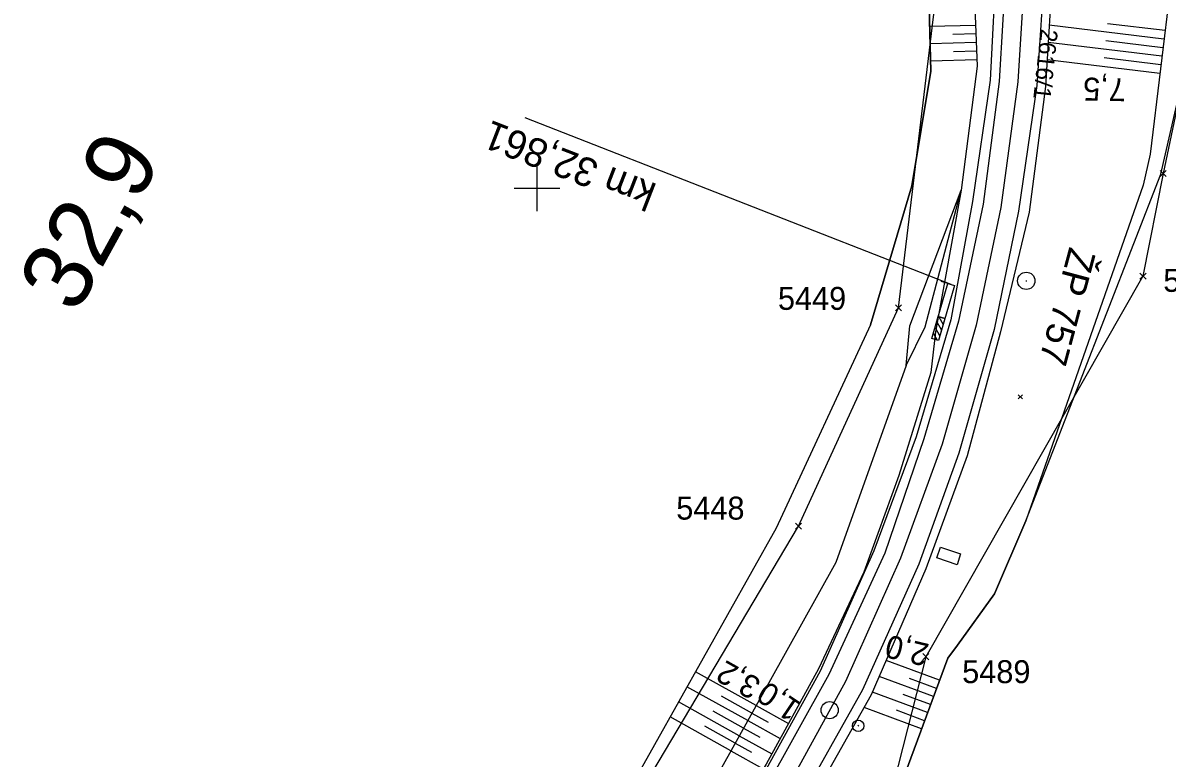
# Model space of a CAD drawing. Extents: x -804166 to -803706, y -1151030 to -1150147.
# Drawn here: x -803944.8 to -803845.1, y -1150649.7 to -1150585.6 of the extents above; entities that cross this region are included whole.
import ezdxf

# ---------------------------------------------------------------- set-up
doc = ezdxf.new("R2010")
doc.units = 0
for name, color, linetype in [('0381KM032-037P - Vrstva 1', 7, 'Continuous'), ('0381KM032-037P - Vrstva 17', 7, 'Continuous'), ('0381KM032-037P - Vrstva 4', 7, 'Continuous'), ('0381KM032-037P - Vrstva 48', 7, 'Continuous'), ('0381KM032-037P - Vrstva 49', 7, 'Continuous'), ('0381KM032-037P - Vrstva 50', 7, 'Continuous'), ('0381KM032-037P - Vrstva 51', 7, 'Continuous'), ('0381KM032-037P - Vrstva 57', 7, 'Continuous'), ('0381KM032-037P - Vrstva 6', 7, 'Continuous'), ('0381KM032-037P - Vrstva 7', 7, 'Continuous'), ('krizky_1000 - Vrstva 1', 7, 'Continuous'), ('szdc - hran DP', 7, 'Continuous'), ('szdc - szdc_cislo', 7, 'Continuous'), ('szdc - szdc_krizek', 7, 'Continuous'), ('vyt_sit - stávající', 7, 'Continuous')]:
    doc.layers.add(name, color=color, linetype=linetype)

msp = doc.modelspace()

# ---------------------------------------------------------------- linework, layer by layer
at = {"layer": '0381KM032-037P - Vrstva 1'}
msp.add_lwpolyline([(-803862.645, -1150536.71), (-803860.057, -1150547.81), (-803858.364, -1150558.718), (-803857.51, -1150569.546), (-803857.425, -1150579.975), (-803858.096, -1150590.725), (-803859.58, -1150601.687), (-803861.73, -1150611.946), (-803864.691, -1150622.329), (-803868.306, -1150632.261), (-803873.118, -1150643.006), (-803878.784, -1150653.323), (-803884.455, -1150662.043), (-803890.68, -1150670.289), (-803894.474, -1150674.768)], dxfattribs=at)
at = {"layer": '0381KM032-037P - Vrstva 17'}
msp.add_lwpolyline([(-803867.911, -1150651.01), (-803864.194, -1150640.965), (-803863.34, -1150639.848), (-803860.107, -1150635.351), (-803857.384, -1150629.008), (-803845.634, -1150598.77), (-803839.769, -1150573.178), (-803837.289, -1150572.72)], dxfattribs=at)
at = {"layer": '0381KM032-037P - Vrstva 4'}
for points in [[(-803872.779, -1150506.875), (-803867.872, -1150516.171), (-803864.004, -1150525.679), (-803860.599, -1150536.286), (-803857.956, -1150547.888), (-803856.113, -1150558.65), (-803855.009, -1150569.422), (-803855.013, -1150580.14), (-803855.681, -1150591.137), (-803857.109, -1150602.102)], [(-803872.779, -1150506.875), (-803868.424, -1150516.34), (-803864.491, -1150525.922), (-803861.191, -1150536.397), (-803858.415, -1150547.949), (-803856.721, -1150558.765), (-803855.706, -1150569.464), (-803855.706, -1150580.041), (-803856.439, -1150591.045), (-803858.016, -1150602.009)], [(-803875.392, -1150508.511), (-803871.454, -1150517.68), (-803867.834, -1150527.236), (-803864.663, -1150537.291), (-803862.152, -1150548.382), (-803860.595, -1150558.999), (-803859.922, -1150569.628), (-803859.947, -1150579.801), (-803860.5, -1150590.58), (-803862.041, -1150601.171)], [(-803859.085, -1150579.867), (-803859.701, -1150590.693), (-803861.107, -1150601.386)], [(-803862.041, -1150601.171), (-803863.934, -1150611.478), (-803866.955, -1150621.666), (-803870.636, -1150631.623), (-803875.322, -1150642.112), (-803880.813, -1150652.073), (-803886.36, -1150660.761), (-803891.5, -1150667.581), (-803892.695, -1150669.921)], [(-803861.107, -1150601.386), (-803863.249, -1150611.592), (-803866.278, -1150621.841), (-803869.683, -1150631.826), (-803874.548, -1150642.393), (-803880.159, -1150652.477), (-803885.847, -1150661.208), (-803892.695, -1150669.921)], [(-803858.016, -1150602.009), (-803860.157, -1150612.315), (-803863.229, -1150623.106), (-803866.722, -1150632.775), (-803871.621, -1150643.742), (-803877.472, -1150654.13), (-803883.137, -1150662.978), (-803889.477, -1150671.458), (-803892.178, -1150675.246)], [(-803857.109, -1150602.102), (-803859.611, -1150612.518), (-803862.49, -1150623.34), (-803866.1, -1150633.182), (-803870.873, -1150644.181), (-803876.806, -1150654.687), (-803882.51, -1150663.405), (-803892.178, -1150675.246)]]:
    msp.add_lwpolyline(points, dxfattribs=at)
at = {"layer": '0381KM032-037P - Vrstva 48'}
for p, q in [((-803861.779, -1150585.81), (-803865.774, -1150585.917)), ((-803845.348, -1150587.012), (-803855.357, -1150585.806)), ((-803845.259, -1150586.267), (-803850.285, -1150585.662)), ((-803861.749, -1150586.559), (-803863.751, -1150586.613)), ((-803861.719, -1150587.309), (-803865.734, -1150587.416)), ((-803845.528, -1150588.501), (-803855.448, -1150587.306)), ((-803845.438, -1150587.757), (-803850.42, -1150587.157)), ((-803861.658, -1150588.808), (-803865.694, -1150588.916)), ((-803861.688, -1150588.058), (-803863.701, -1150588.112)), ((-803845.707, -1150589.991), (-803855.539, -1150588.806)), ((-803845.617, -1150589.246), (-803850.556, -1150588.651)), ((-803864.911, -1150642.902), (-803869.57, -1150641.178)), ((-803880.906, -1150645.106), (-803886.195, -1150642.162)), ((-803865.431, -1150644.309), (-803870.168, -1150642.556)), ((-803865.171, -1150643.606), (-803867.52, -1150642.736)), ((-803881.635, -1150646.417), (-803886.93, -1150643.47)), ((-803882.365, -1150647.727), (-803887.665, -1150644.777)), ((-803881.27, -1150645.761), (-803883.916, -1150644.289)), ((-803865.952, -1150645.716), (-803870.766, -1150643.934)), ((-803865.692, -1150645.012), (-803868.079, -1150644.129)), ((-803882, -1150647.072), (-803884.649, -1150645.598)), ((-803881.27, -1150645.76), (-803879.86, -1150646.545)), ((-803880.905, -1150645.105), (-803878.088, -1150646.673)), ((-803866.473, -1150647.123), (-803871.486, -1150645.267)), ((-803866.212, -1150646.419), (-803868.663, -1150645.512)), ((-803883.094, -1150649.038), (-803888.401, -1150646.085)), ((-803881.635, -1150646.416), (-803878.814, -1150647.986)), ((-803882.729, -1150648.383), (-803885.381, -1150646.907)), ((-803882.364, -1150647.726), (-803879.539, -1150649.299)), ((-803881.999, -1150647.071), (-803880.588, -1150647.857)), ((-803882.729, -1150648.382), (-803881.315, -1150649.168)), ((-803883.093, -1150649.037), (-803880.278, -1150650.604))]:
    msp.add_line(p, q, dxfattribs=at)
at = {"layer": '0381KM032-037P - Vrstva 49'}
for p, q in [((-803870.937, -1150611.902), (-803879.144, -1150629.624)), ((-803858.047, -1150618.024), (-803857.693, -1150618.376)), ((-803857.694, -1150618.023), (-803858.046, -1150618.377))]:
    msp.add_line(p, q, dxfattribs=at)
for points in [[(-803888.13, -1150522.065), (-803877.502, -1150535.708), (-803870.854, -1150543.675), (-803863.849, -1150556.524), (-803862.399, -1150570.315), (-803861.636, -1150589.369), (-803863.02, -1150600.178)], [(-803888.331, -1150532.703), (-803880.592, -1150540.151), (-803872.905, -1150546.743), (-803867.412, -1150556.856), (-803866.176, -1150570.896), (-803865.67, -1150589.811), (-803867.321, -1150599.808), (-803870.937, -1150611.902)], [(-803838.825, -1150566.88), (-803844.043, -1150574.496), (-803844.762, -1150582.145), (-803846.556, -1150597.039), (-803847.173, -1150599.748), (-803857.384, -1150629.008)], [(-803855.009, -1150569.422), (-803855.013, -1150580.14), (-803855.681, -1150591.137), (-803857.109, -1150602.102), (-803859.611, -1150612.518), (-803862.49, -1150623.34), (-803866.1, -1150633.182), (-803870.873, -1150644.181), (-803876.806, -1150654.687), (-803882.51, -1150663.405)], [(-803867.826, -1150615.469), (-803867.512, -1150611.999), (-803863.02, -1150600.178)], [(-803867.826, -1150615.469), (-803866.177, -1150612.082), (-803863.02, -1150600.178)], [(-803863.02, -1150600.178), (-803865.264, -1150612.536), (-803865.684, -1150616.069)], [(-803867.826, -1150615.469), (-803873.958, -1150632.621), (-803887.064, -1150656.172), (-803894.324, -1150662.675), (-803894.538, -1150670.386)], [(-803865.684, -1150616.069), (-803868.473, -1150625.045), (-803871.506, -1150633.468), (-803875.458, -1150641.91), (-803880.036, -1150650.199), (-803884.384, -1150657.469), (-803889.567, -1150664.922), (-803894.538, -1150670.386)], [(-803879.144, -1150629.624), (-803891.889, -1150652.288), (-803898.32, -1150663.448), (-803898.278, -1150667.796), (-803897.353, -1150671.802), (-803897.063, -1150673.395), (-803895.285, -1150678.85), (-803893.718, -1150680.524), (-803892.244, -1150682.081)], [(-803857.384, -1150629.008), (-803860.107, -1150635.351), (-803863.34, -1150639.848), (-803864.194, -1150640.965), (-803867.911, -1150651.01), (-803869.632, -1150654.159), (-803870.889, -1150656.426), (-803877.877, -1150667.643), (-803881.038, -1150676.732), (-803882.094, -1150681.238), (-803882.068, -1150682.623)]]:
    msp.add_lwpolyline(points, dxfattribs=at)
at = {"layer": '0381KM032-037P - Vrstva 50'}
for points in [[(-803870.937, -1150611.902), (-803867.321, -1150599.808), (-803865.67, -1150589.811), (-803866.176, -1150570.896), (-803867.412, -1150556.856), (-803872.905, -1150546.743), (-803880.592, -1150540.151), (-803888.331, -1150532.703), (-803894.19, -1150526.416), (-803900.653, -1150518.475)], [(-803870.937, -1150611.902), (-803879.144, -1150629.624), (-803891.889, -1150652.288), (-803898.32, -1150663.448), (-803898.278, -1150667.796), (-803897.353, -1150671.802), (-803897.063, -1150673.395)]]:
    msp.add_lwpolyline(points, dxfattribs=at)
at = {"layer": '0381KM032-037P - Vrstva 51'}
msp.add_lwpolyline([(-803863.373, -1150632.821), (-803865.148, -1150632.231), (-803864.816, -1150631.297), (-803863.081, -1150631.879), (-803863.373, -1150632.821)], dxfattribs=at)
at = {"layer": '0381KM032-037P - Vrstva 6'}
for p, q in [((-803863.898, -1150608.391), (-803901.037, -1150593.855)), ((-803864.186, -1150608.308), (-803864.763, -1150608.141)), ((-803865.153, -1150611.649), (-803864.743, -1150612.392)), ((-803864.444, -1150611.356), (-803865.02, -1150611.189)), ((-803864.97, -1150611.204), (-803864.596, -1150611.883)), ((-803864.46, -1150611.351), (-803864.448, -1150611.372)), ((-803864.444, -1150611.356), (-803864.444, -1150611.356)), ((-803865.448, -1150612.668), (-803865.133, -1150613.239)), ((-803865.3, -1150612.158), (-803864.891, -1150612.901))]:
    msp.add_line(p, q, dxfattribs=at)
msp.add_lwpolyline([(-803863.61, -1150608.474), (-803865, -1150613.277), (-803865.576, -1150613.111), (-803864.186, -1150608.308), (-803863.61, -1150608.474)], dxfattribs=at)
msp.add_lwpolyline([(-803865.576, -1150613.111), (-803865.02, -1150611.189), (-803864.444, -1150611.356), (-803865, -1150613.277)], close=True, dxfattribs=at)
at = {"layer": '0381KM032-037P - Vrstva 7'}
msp.add_line((-803871.973, -1150646.824), (-803872.021, -1150646.912), dxfattribs=at)
for centre, radius in [((-803874.49, -1150645.505), 0.75), ((-803871.997, -1150646.868), 0.5)]:
    msp.add_circle(centre, radius, dxfattribs=at)
at = {"layer": 'krizky_1000 - Vrstva 1'}
for points in [[(-803900, -1150598), (-803900, -1150602)], [(-803902, -1150600), (-803898, -1150600)]]:
    msp.add_lwpolyline(points, dxfattribs=at)
at = {"layer": 'szdc - hran DP'}
for p, q in [((-803868.49, -1150610.44), (-803863.95, -1150572.75)), ((-803842.82, -1150586.3), (-803845.41, -1150598.72)), ((-803845.41, -1150598.72), (-803847.18, -1150607.67)), ((-803847.18, -1150607.67), (-803866.11, -1150640.84)), ((-803877.2, -1150629.46), (-803868.49, -1150610.44)), ((-803894.67, -1150658.87), (-803877.2, -1150629.46)), ((-803866.11, -1150640.84), (-803869.51, -1150654.24))]:
    msp.add_line(p, q, dxfattribs=at)
at = {"layer": 'szdc - szdc_krizek'}
for p, q in [((-803845.145, -1150598.985), (-803845.676, -1150598.455)), ((-803845.676, -1150598.985), (-803845.145, -1150598.455)), ((-803846.915, -1150607.935), (-803847.446, -1150607.405)), ((-803847.446, -1150607.935), (-803846.915, -1150607.405)), ((-803868.225, -1150610.705), (-803868.756, -1150610.175)), ((-803868.756, -1150610.705), (-803868.225, -1150610.175)), ((-803876.935, -1150629.725), (-803877.466, -1150629.195)), ((-803877.466, -1150629.725), (-803876.935, -1150629.195)), ((-803865.845, -1150641.105), (-803866.376, -1150640.575)), ((-803866.376, -1150641.105), (-803865.845, -1150640.575))]:
    msp.add_line(p, q, dxfattribs=at)
at = {"layer": 'vyt_sit - stávající'}
msp.add_line((-803857.401, -1150608.078), (-803857.301, -1150608.078), dxfattribs=at)
msp.add_circle((-803857.351, -1150608.078), 0.756, dxfattribs=at)

# ---------------------------------------------------------------- texts
at = {"layer": '0381KM032-037P - Vrstva 48'}
for s, rotation, p in [('7,5', 179.00475, (-803848.659, -1150590.424)), ('2,0', 166.54164, (-803865.72, -1150639.769)), ('3,2', 150.64897, (-803880.336, -1150642.91)), ('1,0', 145.90431, (-803876.829, -1150644.97))]:
    msp.add_text(s, height=2, rotation=rotation, dxfattribs=at).set_placement(p)
at = {"layer": '0381KM032-037P - Vrstva 57'}
msp.add_text('2616/1', height=1.5, rotation=263.79604, dxfattribs=at).set_placement((-803856.079, -1150586.074))
at = {"layer": '0381KM032-037P - Vrstva 6'}
msp.add_text('km 32,861', height=2.5, rotation=158.86045, dxfattribs=at).set_placement((-803889.433, -1150599.681))
at = {"layer": '0381KM032-037P - Vrstva 7'}
msp.add_text('32,9', height=6, rotation=61.22482, dxfattribs=at).set_placement((-803940.167, -1150611.093))
at = {"layer": 'szdc - szdc_cislo'}
for s, p in [('5488', (-803845.41, -1150609.039)), ('5449', (-803878.999, -1150610.608)), ('5448', (-803887.86, -1150628.892)), ('5489', (-803862.939, -1150643.147))]:
    msp.add_text(s, height=2, dxfattribs=at).set_placement(p)
at = {"layer": 'vyt_sit - stávající'}
msp.add_text('ŽP 757', height=2.4, rotation=255, dxfattribs=at).set_placement((-803853.581, -1150605.05))

doc.saveas('drawing.dxf')
